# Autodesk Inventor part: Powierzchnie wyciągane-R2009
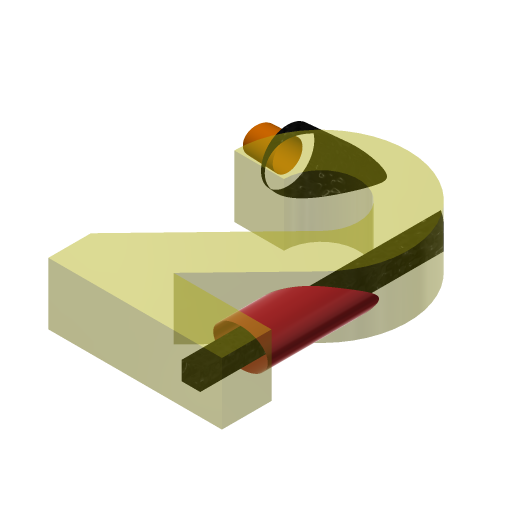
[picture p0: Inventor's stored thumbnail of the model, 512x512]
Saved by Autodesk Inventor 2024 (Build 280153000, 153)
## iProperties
Company: ATC
Created: 2023-03
Part Number: Powierzchnie wyciągane-R2009
Document SubType Name: Modeling
Designer: Andrzej Jaskulski
Manufacturer: Standard
Standards Organization: Custom
Material: Kurs-AJ
Density: 1 g/cm^3
Appearance: Przezroczyste — żółte
Checked By: A.J.
Engr Approved By: Andrzej Jaskulski
Mfg Approved By: Andrzej Jaskulski
Authority: A.J.
Title: A.J.: Kurs R2024-MEP
Author: Andrzej Jaskulski
Revision Number: 1/24
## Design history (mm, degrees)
sketch "Zarys dwójki"
  geometry: L1 (0, 0)-(140, 0); L2 (140, 0)-(140, 40); L3 (140, 40)-(61.086, 40); L4 (0, 0)-(0, 34.326); L5 (0, 34.326)-(91.58, 129.16); L6 (61.086, 40)-(120.354, 101.374); L7 (40, 150)-(0, 150); A1 r 30 centre (70, 150) between (91.58, 129.16) and (40, 150); A2 r 70 centre (70, 150) between (120.354, 101.374) and (0, 150)
  constraints: 14 end point, 4 point on circle, 3 perpendicular, 2 centre point, 2 parallel, 2 tangent, 1 coincident, 1 horizontal, 1 point on line, 1 other
  dimensions: "d0" = 140 distance of L1.start L1.end; "d1" = 150 distance from line of A1.centre L1; "d2" = 70 radius of A2; "d3" = 30 radius of A1; "d4" = 70 distance from line of L4 A1.centre; "d5" = 46 deg angle of L6 L3; "d6" = 40 distance of L1.end L2.end
extrude "Dwójka" new body sketch "Zarys dwójki" distance "d7" = 50; taper "d8" = 0 deg
node "Odsunięta od Stycznej do Walca"
  node "Styczna do Walca"
node "Oś powierzchni walcowej"
sketch "Elipsa i Kwadrat"
  geometry: L1 (140, 50)-(0, 50) reference; L2 (0, 0)-(0, 50) reference; L3 (107.5, 32.5)-(122.5, 32.5); L4 (122.5, 32.5)-(122.5, 17.5); L5 (122.5, 17.5)-(107.5, 17.5); L6 (107.5, 17.5)-(107.5, 32.5); C1 r 10 at (115, 25); 3 further points
  constraints: 8 end point, 3 midpoint, 2 horizontal alignment, 2 parallel, 2 perpendicular, 1 centre point, 1 horizontal, 1 vertical alignment, 1 other
sketch "Okręgi"
  geometry: L1 (0, 150)-(50, 150) reference; C1 r 12 at (25, 193); C2 r 21.5 at (25, 193); 1 further point
  constraints: 2 centre point, 1 coincident, 1 midpoint, 1 vertical alignment
feature "Pow. 1" dims "d29" = 10, "d30" = 4 deg
feature "Pow. 2" dims "d31" = 10, "d32" = -2 deg
feature "Pow. 3" dims "d33" = 10, "d34" = 0
feature "Pow. 4" dims "d35" = 10, "d36" = 0
node "Bryła1"
node "Korpusy bryłowe"
node "Korpusy powierzchniowe"
body "Srf1"
body "Srf2"
body "Srf3"
body "Srf4"
